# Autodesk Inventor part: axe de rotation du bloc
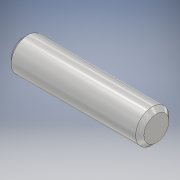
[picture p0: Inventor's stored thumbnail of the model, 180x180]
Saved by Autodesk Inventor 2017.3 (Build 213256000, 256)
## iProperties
Part Number: axe de rotation du bloc
Material: Aluminium 6061
Document SubType Name: Modeling
Designer: ficho
Density: 2.7 g/cm^3
Appearance: Aluminum - Poli
Author: ficho
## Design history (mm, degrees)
sketch "Esquisse1"
  geometry: L1 (0, 0)-(8, 0); L2 (8, 0)-(8, 0.75); L3 (7.75, 1)-(0.25, 1); L4 (0, 0.75)-(0, 0); L5 (0.25, 1)-(0, 0.75); L6 (7.75, 1)-(8, 0.75); 2 further points
  constraints: 12 end point, 4 point on line, 2 parallel, 1 horizontal, 1 perpendicular
  dimensions: "d0" = 8 distance of point (0, 1) point (8, 1); "d1" = 1 distance of point (8, 1) L1.end; "d2" = 0.25 distance of L3.end point (0, 1); "d3" = 0.25 distance of L4.start point (0, 1) (= d2); "d4" = 0.25 distance of L3.start point (8, 1) (= d2); "d5" = 0.25 distance of L2.end point (8, 1) (= d4)
revolve "Révolution1" sketch "Esquisse1" stored, may be unused: angle "d6" = 90 deg
node "Solide1"
